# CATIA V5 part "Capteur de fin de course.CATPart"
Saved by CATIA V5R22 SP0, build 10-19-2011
Part number: Capteur de fin de course
Revision: ANY
Definition: UNKNOWN
Nomenclature: Capteur de fin de course
Source: Unknown
Bounding box of the stored display mesh (mm): x -23.509 to 13.9, y -7.95 to 15.419, z 0 to 9.5
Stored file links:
  D:\PER\CAO_PER_MODIF_2025\CAO_PER_pick&place_2024P\Sous_Ensemble_Flacon\Capteur de fin de course.CATPart
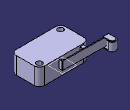
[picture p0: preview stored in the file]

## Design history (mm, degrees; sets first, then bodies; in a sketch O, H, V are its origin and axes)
Set1
  Sketch1 on face of Solid1, origin (0, 0, 9.5), H (1, 0, 0), V (0, 1, 0)
    circle A1 centre (-21.4479, 13.4192) radius 2
    reference projected line E1 (2.7544, 9.9963) -> (-23.5, 10.4545) from edge [face of Solid1 | face of Solid1]
    reference projected line E2 (-23.5, 10.4545) -> (-23.5087, 9.9546) from edge [face of Solid1 | face of Solid1]
    distance E1 A1 = 5
    radius A1 = 2
    distance E2 A1 = 0
Body1 "Boss.-Extru.2" (main body)
  Solid1: solid without history
  Pad1: profile Sketch1, direction (0, 0, -1), length 5.25
  Sketch2 on face of Solid1, origin (-23.6753, 0.4133, 0), H (-0.0175, -0.9998, 0), V (0, 0, 1)
    line L1 (-10.0521, 8.75) -> (-16.3953, 8.75)
    line L2 (-16.3953, 8.75) -> (-16.3953, 9.9301)
    line L3 (-16.3953, 9.9301) -> (-10.0521, 9.9301)
    line L4 (-10.0521, 9.9301) -> (-10.0521, 8.75)
    reference projected line E1 (-10.0428, 8.75) -> (-9.5428, 8.75) from edge [face of Solid1 | face of Solid1]
    horizontal: L1 H, L3 H
    vertical: L2 V, L4 V
    coincidence: L1 E1
  Pocket1: profile Sketch2, direction (0.9998, -0.0175, 0), through (limit type 3)
  Sketch3 on face of Pocket1 from Sketch2.L1, origin (0, 0, 8.75), H (1, 0, 0), V (0, 1, 0)
    line L1 (-22.9479, 9.9448) -> (-19.9479, 9.8925)
    line L2 (-19.9479, 9.8925) -> (-19.9479, 13.4192)
    line L3 (-22.9479, 13.4192) -> (-22.9479, 9.9448)
    point P3 (-19.9479, 12.8439)
    arc A1 centre (-21.4479, 13.4192) radius 1.5 from (-19.9479, 13.4192) to (-22.9479, 13.4192) ccw
    point P4 (-21.4479, 13.4192)
    reference projected circle E1 centre (-21.4479, 13.4192) radius 2 from edge [face of Pad1 from Sketch1.A1 | face of Pocket1 from Sketch2.L1]
    reference projected line E2 (-23.5087, 9.9546) -> (2.2544, 9.5049) from edge [face of Solid1 | face of Solid1]
    distance L2 L3 = 3
    vertical: L2 V, L3 V
    coincidence: P3 L2, L1 E2
    tangency: A1 L2, A1 L3
    concentricity: P4 E1
  Pad2: profile Sketch3, direction (0, 0, 1), length 0.5
  Plane1: type Offset, RefPlane face of Solid1, Offset 2.25
  Mirror1: of Pad2, about Plane1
